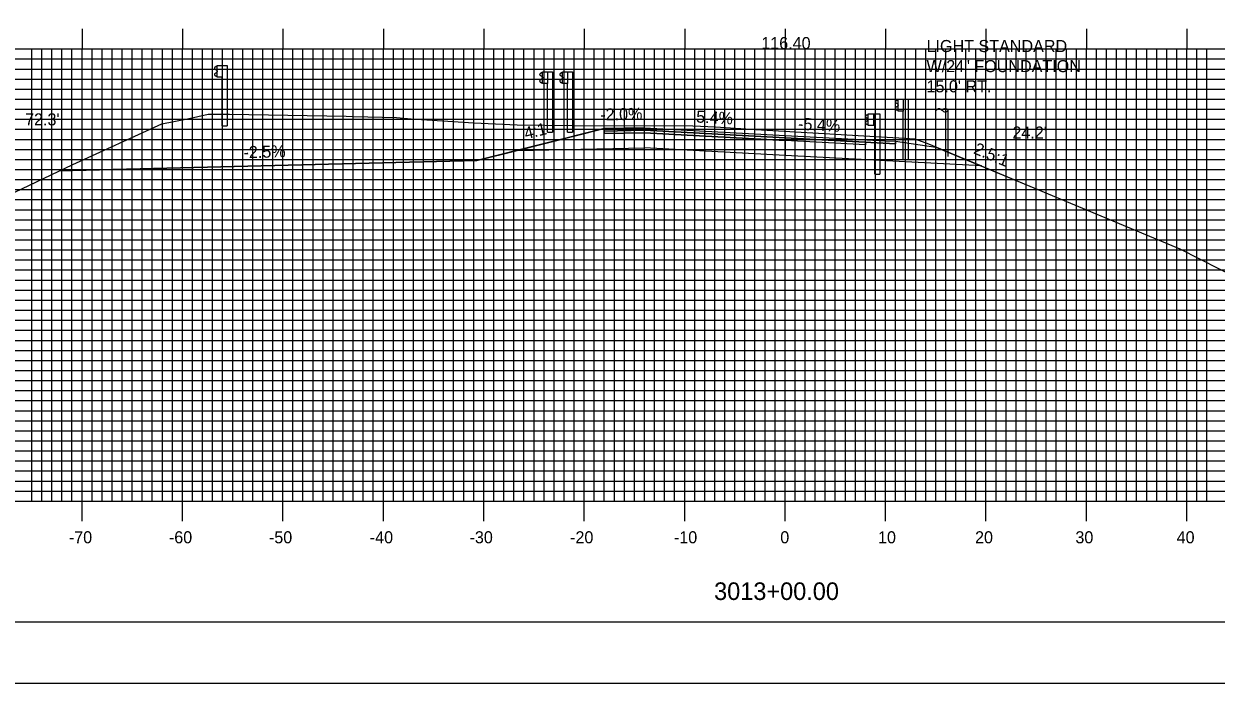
# Model space of a CAD drawing. Extents: x 1684405 to 1684749, y 461260 to 461480.
# Drawn here: x 1684495.4 to 1684614.1, y 461260 to 461325.6 of the extents above; entities that cross this region are included whole.
import ezdxf

# ---------------------------------------------------------------- set-up
doc = ezdxf.new("R2010")
doc.units = 0
for name, color, linetype in [('ANNOTATION', 7, 'Continuous'), ('BORDER', 7, 'Continuous'), ('D_Guardrail_Beam_Rt', 7, 'Continuous'), ('D_Roadway_Centerline', 7, 'Continuous'), ('D_Roadway_Centerline_Text', 7, 'Continuous'), ('D_Roadway_Edge_Shoulder', 7, 'Continuous'), ('D_Roadway_Edge_TW', 7, 'Continuous'), ('D_Roadway_Pavement', 7, 'Continuous'), ('D_Roadway_SlopeLines', 7, 'Continuous'), ('D_Roadway_SubGrade', 7, 'Continuous'), ('D_Text_Standard', 7, 'Continuous'), ('H_V ANNOTATION', 7, 'Continuous'), ('M_Guardrail', 7, 'Continuous'), ('M_Roadway_Centerline', 7, 'Continuous'), ('MAJOR', 7, 'Continuous'), ('MINOR', 7, 'Continuous'), ('PLOT BOUNDARY', 7, 'Continuous'), ('S_Roadway_Centerline', 7, 'Continuous'), ('S_Utilities_Pole_StreetLight', 7, 'Continuous')]:
    doc.layers.add(name, color=color, linetype=linetype)

msp = doc.modelspace()

# ---------------------------------------------------------------- linework, layer by layer
at = {"layer": 'BORDER'}
msp.add_lwpolyline([(1684421.6, 461266.07), (1684741.6, 461266.07), (1684741.6, 461476.07), (1684421.6, 461476.07)], close=True, dxfattribs=at)
at = {"layer": 'D_Guardrail_Beam_Rt'}
for p, q in [((1684579.38, 461316.52), (1684579.24, 461316.42)), ((1684579.24, 461316.27), (1684579.44, 461316.14)), ((1684579.44, 461315.94), (1684579.24, 461315.8)), ((1684579.47, 461316.54), (1684579.4, 461316.52)), ((1684579.47, 461316.62), (1684580.16, 461316.62)), ((1684579.47, 461315.46), (1684579.47, 461316.62)), ((1684579.47, 461316.07), (1684579.47, 461316)), ((1684579.99, 461316.62), (1684579.99, 461315.46)), ((1684580.1, 461316.62), (1684580.1, 461315.46)), ((1684580.16, 461316.62), (1684580.63, 461316.62)), ((1684580.16, 461316.62), (1684580.16, 461315.46)), ((1684580.63, 461316.62), (1684580.63, 461310.62)), ((1684579.24, 461315.66), (1684579.38, 461315.56)), ((1684579.4, 461315.55), (1684579.47, 461315.54)), ((1684580.16, 461315.46), (1684579.47, 461315.46)), ((1684580.14, 461310.62), (1684580.14, 461315.46)), ((1684580.14, 461310.62), (1684580.63, 461310.62))]:
    msp.add_line(p, q, dxfattribs=at)
for centre, major_axis, start_param, end_param in [((1684579.29, 461316.35), (-0.0877, 0), 5.323254, 7.243116), ((1684579.29, 461315.73), (-0.0877, 0), 5.323254, 7.243116), ((1684579.41, 461316.48), (-0.0417, 0), 4.907132, 5.323254), ((1684579.39, 461316.07), (0.0789, 0), 0, 0.959931), ((1684579.39, 461316), (0.0789, 0), 5.323254, 6.283185), ((1684579.41, 461315.59), (-0.0417, 0), 0.959931, 1.376053)]:
    msp.add_ellipse(centre, major_axis=major_axis, ratio=0.995501, start_param=start_param, end_param=end_param, dxfattribs=at)
at = {"layer": 'D_Roadway_Centerline'}
msp.add_lwpolyline([(1684498.93, 461310.93), (1684540.51, 461311.97), (1684544.51, 461312.97), (1684553.2, 461315.15), (1684557.2, 461315.23), (1684571.2, 461314.47), (1684581.2, 461313.93), (1684582.2, 461313.88), (1684586.2, 461313.31), (1684595.4, 461309.48)], dxfattribs=at)
at = {"layer": 'D_Roadway_Edge_Shoulder'}
for points in [[(1684557.2, 461315.23), (1684553.2, 461315.15), (1684553.2, 461314.9), (1684557.2, 461314.98)], [(1684571.2, 461314.47), (1684581.2, 461313.93), (1684581.2, 461313.93), (1684582.2, 461313.88), (1684582.2, 461313.63), (1684571.2, 461314.22)], [(1684571.2, 461314.22), (1684579.2, 461313.79), (1684579.2, 461313.54), (1684571.2, 461313.97)]]:
    msp.add_lwpolyline(points, close=True, dxfattribs=at)
at = {"layer": 'D_Roadway_Edge_TW'}
msp.add_lwpolyline([(1684557.2, 461315.23), (1684571.2, 461314.47), (1684571.2, 461314.22), (1684557.2, 461314.98)], close=True, dxfattribs=at)
at = {"layer": 'D_Roadway_Pavement'}
for points in [[(1684557.2, 461314.98), (1684553.2, 461314.9), (1684553.2, 461314.65), (1684557.2, 461314.73)], [(1684557.2, 461314.98), (1684571.2, 461314.22), (1684571.2, 461313.97), (1684557.2, 461314.73)]]:
    msp.add_lwpolyline(points, close=True, dxfattribs=at)
msp.add_lwpolyline([(1684571.2, 461314.22), (1684571.2, 461313.97)], dxfattribs=at)
msp.add_lwpolyline([(1684571.2, 461314.22), (1684571.2, 461313.97)], dxfattribs=at)
msp.add_lwpolyline([(1684571.2, 461314.22), (1684571.2, 461313.97)], dxfattribs=at)
at = {"layer": 'D_Roadway_SlopeLines'}
for points in [[(1684553.2, 461315.15), (1684540.51, 461311.97)], [(1684540.51, 461311.97), (1684498.93, 461310.93)]]:
    msp.add_lwpolyline(points, dxfattribs=at)
at = {"layer": 'D_Roadway_SubGrade'}
for points in [[(1684557.2, 461314.73), (1684553.2, 461314.65), (1684553.2, 461314.9), (1684553.2, 461315.15), (1684544.51, 461312.97), (1684557.2, 461313.23)], [(1684557.2, 461314.73), (1684571.2, 461313.97), (1684571.2, 461312.47), (1684557.2, 461313.23)], [(1684571.2, 461313.97), (1684571.2, 461314.22), (1684582.2, 461313.63), (1684582.2, 461313.88), (1684586.2, 461313.31), (1684590.75, 461311.42), (1684571.2, 461312.47)]]:
    msp.add_lwpolyline(points, close=True, dxfattribs=at)
at = {"layer": 'M_Guardrail'}
for p, q in [((1684514.56, 461321.33), (1684514.42, 461321.23)), ((1684514.42, 461321.09), (1684514.61, 461320.95)), ((1684514.61, 461320.73), (1684514.42, 461320.6)), ((1684514.66, 461321.35), (1684514.58, 461321.34)), ((1684514.65, 461320.89), (1684514.65, 461320.8)), ((1684514.66, 461321.43), (1684515.15, 461321.43)), ((1684514.66, 461320.26), (1684514.66, 461321.43)), ((1684515.15, 461321.43), (1684515.64, 461321.43)), ((1684515.15, 461321.43), (1684515.15, 461320.26)), ((1684515.64, 461321.43), (1684515.64, 461315.43)), ((1684546.95, 461320.69), (1684546.8, 461320.59)), ((1684547.05, 461320.71), (1684546.96, 461320.7)), ((1684547.05, 461320.79), (1684547.54, 461320.79)), ((1684547.05, 461319.62), (1684547.05, 461320.79)), ((1684547.54, 461320.79), (1684548.03, 461320.79)), ((1684547.54, 461320.79), (1684547.54, 461319.62)), ((1684548.03, 461320.79), (1684548.03, 461314.79)), ((1684548.95, 461320.69), (1684548.8, 461320.59)), ((1684549.05, 461320.71), (1684548.96, 461320.7)), ((1684549.05, 461320.79), (1684549.54, 461320.79)), ((1684549.05, 461319.62), (1684549.05, 461320.79)), ((1684549.54, 461320.79), (1684550.03, 461320.79)), ((1684549.54, 461320.79), (1684549.54, 461319.62)), ((1684550.03, 461320.79), (1684550.03, 461314.79)), ((1684514.42, 461320.45), (1684514.56, 461320.35)), ((1684514.58, 461320.35), (1684514.66, 461320.33)), ((1684515.15, 461320.26), (1684514.66, 461320.26)), ((1684515.15, 461315.43), (1684515.15, 461320.26)), ((1684546.8, 461320.45), (1684547, 461320.31)), ((1684547, 461320.09), (1684546.8, 461319.96)), ((1684546.8, 461319.81), (1684546.95, 461319.71)), ((1684546.96, 461319.71), (1684547.05, 461319.69)), ((1684547.03, 461320.25), (1684547.03, 461320.16)), ((1684547.54, 461319.62), (1684547.05, 461319.62)), ((1684547.54, 461314.79), (1684547.54, 461319.62)), ((1684548.8, 461320.45), (1684549, 461320.31)), ((1684549, 461320.09), (1684548.8, 461319.96)), ((1684548.8, 461319.81), (1684548.95, 461319.71)), ((1684548.96, 461319.71), (1684549.05, 461319.69)), ((1684549.03, 461320.25), (1684549.03, 461320.16)), ((1684549.54, 461319.62), (1684549.05, 461319.62)), ((1684549.54, 461314.79), (1684549.54, 461319.62)), ((1684582.37, 461317.96), (1684582.23, 461317.86)), ((1684582.23, 461317.72), (1684582.43, 461317.59)), ((1684582.43, 461317.37), (1684582.23, 461317.23)), ((1684582.23, 461317.09), (1684582.37, 461316.99)), ((1684582.47, 461317.99), (1684582.39, 461317.97)), ((1684582.46, 461317.52), (1684582.46, 461317.43)), ((1684582.47, 461318.06), (1684582.96, 461318.06)), ((1684582.47, 461316.89), (1684582.47, 461318.06)), ((1684582.96, 461318.06), (1684583.45, 461318.06)), ((1684582.96, 461318.06), (1684582.96, 461316.89)), ((1684583.45, 461318.06), (1684583.45, 461312.06)), ((1684582.39, 461316.98), (1684582.47, 461316.96)), ((1684582.96, 461316.89), (1684582.47, 461316.89)), ((1684582.96, 461312.06), (1684582.96, 461316.89)), ((1684515.15, 461315.43), (1684515.64, 461315.43)), ((1684547.54, 461314.79), (1684548.03, 461314.79)), ((1684549.54, 461314.79), (1684550.03, 461314.79)), ((1684582.96, 461312.06), (1684583.45, 461312.06))]:
    msp.add_line(p, q, dxfattribs=at)
for centre, major_axis, start_param, end_param in [((1684514.47, 461321.16), (-0.0877, 0), 5.323254, 7.243116), ((1684514.47, 461320.53), (-0.0877, 0), 5.323254, 7.243116), ((1684514.59, 461321.3), (-0.0417, 0), 4.886922, 5.323254), ((1684514.57, 461320.89), (0.0789, 0), 0, 0.959931), ((1684514.57, 461320.8), (0.0789, 0), 5.323254, 6.283185), ((1684546.85, 461320.52), (-0.0877, 0), 5.323254, 7.243116), ((1684546.97, 461320.66), (-0.0417, 0), 4.886922, 5.323254), ((1684548.85, 461320.52), (-0.0877, 0), 5.323254, 7.243116), ((1684548.97, 461320.66), (-0.0417, 0), 4.886922, 5.323254), ((1684514.59, 461320.39), (-0.0417, 0), 0.959931, 1.396263), ((1684546.85, 461319.88), (-0.0877, 0), 5.323254, 7.243116), ((1684546.97, 461319.75), (-0.0417, 0), 0.959931, 1.396263), ((1684546.95, 461320.25), (0.0789, 0), 0, 0.959931), ((1684546.95, 461320.16), (0.0789, 0), 5.323254, 6.283185), ((1684548.85, 461319.89), (-0.0877, 0), 5.323254, 7.243116), ((1684548.97, 461319.75), (-0.0417, 0), 0.959931, 1.396263), ((1684548.95, 461320.25), (0.0789, 0), 0, 0.959931), ((1684548.95, 461320.16), (0.0789, 0), 5.323254, 6.283185), ((1684582.28, 461317.79), (-0.0877, 0), 5.323254, 7.243116), ((1684582.28, 461317.16), (-0.0877, 0), 5.323254, 7.243116), ((1684582.4, 461317.93), (-0.0417, 0), 4.886922, 5.323254), ((1684582.4, 461317.02), (-0.0417, 0), 0.959931, 1.396263), ((1684582.38, 461317.52), (0.0789, 0), 0, 0.959931), ((1684582.38, 461317.43), (0.0789, 0), 5.323254, 6.283185)]:
    msp.add_ellipse(centre, major_axis=major_axis, ratio=0.995501, start_param=start_param, end_param=end_param, dxfattribs=at)
at = {"layer": 'MAJOR'}
for p, q in [((1684501.2, 461325.08), (1684501.2, 461323.07)), ((1684511.2, 461325.08), (1684511.2, 461323.07)), ((1684521.2, 461325.08), (1684521.2, 461323.07)), ((1684531.2, 461325.08), (1684531.2, 461323.07)), ((1684541.2, 461325.08), (1684541.2, 461323.07)), ((1684551.2, 461325.08), (1684551.2, 461323.07)), ((1684561.2, 461325.08), (1684561.2, 461323.07)), ((1684571.2, 461325.08), (1684571.2, 461323.07)), ((1684581.2, 461325.08), (1684581.2, 461323.07)), ((1684591.2, 461325.08), (1684591.2, 461323.07)), ((1684601.2, 461325.08), (1684601.2, 461323.07)), ((1684611.2, 461325.08), (1684611.2, 461323.07)), ((1684431.2, 461323.07), (1684711.2, 461323.07)), ((1684431.2, 461323.07), (1684711.2, 461323.07)), ((1684501.2, 461278.07), (1684501.2, 461323.07)), ((1684511.2, 461278.07), (1684511.2, 461323.07)), ((1684521.2, 461278.07), (1684521.2, 461323.07)), ((1684531.2, 461278.07), (1684531.2, 461323.07)), ((1684541.2, 461278.07), (1684541.2, 461323.07)), ((1684551.2, 461278.07), (1684551.2, 461323.07)), ((1684561.2, 461278.07), (1684561.2, 461323.07)), ((1684571.2, 461278.07), (1684571.2, 461323.07)), ((1684581.2, 461278.07), (1684581.2, 461323.07)), ((1684591.2, 461278.07), (1684591.2, 461323.07)), ((1684601.2, 461278.07), (1684601.2, 461323.07)), ((1684611.2, 461278.07), (1684611.2, 461323.07)), ((1684431.2, 461318.07), (1684711.2, 461318.07)), ((1684431.2, 461313.07), (1684711.2, 461313.07)), ((1684431.2, 461308.07), (1684711.2, 461308.07)), ((1684431.2, 461303.07), (1684711.2, 461303.07)), ((1684431.2, 461298.07), (1684711.2, 461298.07)), ((1684431.2, 461293.07), (1684711.2, 461293.07)), ((1684431.2, 461288.07), (1684711.2, 461288.07)), ((1684431.2, 461283.07), (1684711.2, 461283.07)), ((1684431.2, 461278.07), (1684711.2, 461278.07)), ((1684431.2, 461278.07), (1684711.2, 461278.07)), ((1684501.2, 461276.07), (1684501.2, 461278.07)), ((1684511.2, 461276.07), (1684511.2, 461278.07)), ((1684521.2, 461276.07), (1684521.2, 461278.07)), ((1684531.2, 461276.07), (1684531.2, 461278.07)), ((1684541.2, 461276.07), (1684541.2, 461278.07)), ((1684551.2, 461276.07), (1684551.2, 461278.07)), ((1684561.2, 461276.07), (1684561.2, 461278.07)), ((1684571.2, 461276.07), (1684571.2, 461278.07)), ((1684581.2, 461276.07), (1684581.2, 461278.07)), ((1684591.2, 461276.07), (1684591.2, 461278.07)), ((1684601.2, 461276.07), (1684601.2, 461278.07)), ((1684611.2, 461276.07), (1684611.2, 461278.07))]:
    msp.add_line(p, q, dxfattribs=at)
at = {"layer": 'MINOR'}
for p, q in [((1684496.2, 461278.07), (1684496.2, 461323.07)), ((1684497.2, 461278.07), (1684497.2, 461323.07)), ((1684498.2, 461278.07), (1684498.2, 461323.07)), ((1684499.2, 461278.07), (1684499.2, 461323.07)), ((1684500.2, 461278.07), (1684500.2, 461323.07)), ((1684502.2, 461278.07), (1684502.2, 461323.07)), ((1684503.2, 461278.07), (1684503.2, 461323.07)), ((1684504.2, 461278.07), (1684504.2, 461323.07)), ((1684505.2, 461278.07), (1684505.2, 461323.07)), ((1684506.2, 461278.07), (1684506.2, 461323.07)), ((1684507.2, 461278.07), (1684507.2, 461323.07)), ((1684508.2, 461278.07), (1684508.2, 461323.07)), ((1684509.2, 461278.07), (1684509.2, 461323.07)), ((1684510.2, 461278.07), (1684510.2, 461323.07)), ((1684512.2, 461278.07), (1684512.2, 461323.07)), ((1684513.2, 461278.07), (1684513.2, 461323.07)), ((1684514.2, 461278.07), (1684514.2, 461323.07)), ((1684515.2, 461278.07), (1684515.2, 461323.07)), ((1684516.2, 461278.07), (1684516.2, 461323.07)), ((1684517.2, 461278.07), (1684517.2, 461323.07)), ((1684518.2, 461278.07), (1684518.2, 461323.07)), ((1684519.2, 461278.07), (1684519.2, 461323.07)), ((1684520.2, 461278.07), (1684520.2, 461323.07)), ((1684522.2, 461278.07), (1684522.2, 461323.07)), ((1684523.2, 461278.07), (1684523.2, 461323.07)), ((1684524.2, 461278.07), (1684524.2, 461323.07)), ((1684525.2, 461278.07), (1684525.2, 461323.07)), ((1684526.2, 461278.07), (1684526.2, 461323.07)), ((1684527.2, 461278.07), (1684527.2, 461323.07)), ((1684528.2, 461278.07), (1684528.2, 461323.07)), ((1684529.2, 461278.07), (1684529.2, 461323.07)), ((1684530.2, 461278.07), (1684530.2, 461323.07)), ((1684532.2, 461278.07), (1684532.2, 461323.07)), ((1684533.2, 461278.07), (1684533.2, 461323.07)), ((1684534.2, 461278.07), (1684534.2, 461323.07)), ((1684535.2, 461278.07), (1684535.2, 461323.07)), ((1684536.2, 461278.07), (1684536.2, 461323.07)), ((1684537.2, 461278.07), (1684537.2, 461323.07)), ((1684538.2, 461278.07), (1684538.2, 461323.07)), ((1684539.2, 461278.07), (1684539.2, 461323.07)), ((1684540.2, 461278.07), (1684540.2, 461323.07)), ((1684542.2, 461278.07), (1684542.2, 461323.07)), ((1684543.2, 461278.07), (1684543.2, 461323.07)), ((1684544.2, 461278.07), (1684544.2, 461323.07)), ((1684545.2, 461278.07), (1684545.2, 461323.07)), ((1684546.2, 461278.07), (1684546.2, 461323.07)), ((1684547.2, 461278.07), (1684547.2, 461323.07)), ((1684548.2, 461278.07), (1684548.2, 461323.07)), ((1684549.2, 461278.07), (1684549.2, 461323.07)), ((1684550.2, 461278.07), (1684550.2, 461323.07)), ((1684552.2, 461278.07), (1684552.2, 461323.07)), ((1684553.2, 461278.07), (1684553.2, 461323.07)), ((1684554.2, 461278.07), (1684554.2, 461323.07)), ((1684555.2, 461278.07), (1684555.2, 461323.07)), ((1684556.2, 461278.07), (1684556.2, 461323.07)), ((1684557.2, 461278.07), (1684557.2, 461323.07)), ((1684558.2, 461278.07), (1684558.2, 461323.07)), ((1684559.2, 461278.07), (1684559.2, 461323.07)), ((1684560.2, 461278.07), (1684560.2, 461323.07)), ((1684562.2, 461278.07), (1684562.2, 461323.07)), ((1684563.2, 461278.07), (1684563.2, 461323.07)), ((1684564.2, 461278.07), (1684564.2, 461323.07)), ((1684565.2, 461278.07), (1684565.2, 461323.07)), ((1684566.2, 461278.07), (1684566.2, 461323.07)), ((1684567.2, 461278.07), (1684567.2, 461323.07)), ((1684568.2, 461278.07), (1684568.2, 461323.07)), ((1684569.2, 461278.07), (1684569.2, 461323.07)), ((1684570.2, 461278.07), (1684570.2, 461323.07)), ((1684572.2, 461278.07), (1684572.2, 461323.07)), ((1684573.2, 461278.07), (1684573.2, 461323.07)), ((1684574.2, 461278.07), (1684574.2, 461323.07)), ((1684575.2, 461278.07), (1684575.2, 461323.07)), ((1684576.2, 461278.07), (1684576.2, 461323.07)), ((1684577.2, 461278.07), (1684577.2, 461323.07)), ((1684578.2, 461278.07), (1684578.2, 461323.07)), ((1684579.2, 461278.07), (1684579.2, 461323.07)), ((1684580.2, 461278.07), (1684580.2, 461323.07)), ((1684582.2, 461278.07), (1684582.2, 461323.07)), ((1684583.2, 461278.07), (1684583.2, 461323.07)), ((1684584.2, 461278.07), (1684584.2, 461323.07)), ((1684585.2, 461278.07), (1684585.2, 461323.07)), ((1684586.2, 461278.07), (1684586.2, 461323.07)), ((1684587.2, 461278.07), (1684587.2, 461323.07)), ((1684588.2, 461278.07), (1684588.2, 461323.07)), ((1684589.2, 461278.07), (1684589.2, 461323.07)), ((1684590.2, 461278.07), (1684590.2, 461323.07)), ((1684592.2, 461278.07), (1684592.2, 461323.07)), ((1684593.2, 461278.07), (1684593.2, 461323.07)), ((1684594.2, 461278.07), (1684594.2, 461323.07)), ((1684595.2, 461278.07), (1684595.2, 461323.07)), ((1684596.2, 461278.07), (1684596.2, 461323.07)), ((1684597.2, 461278.07), (1684597.2, 461323.07)), ((1684598.2, 461278.07), (1684598.2, 461323.07)), ((1684599.2, 461278.07), (1684599.2, 461323.07)), ((1684600.2, 461278.07), (1684600.2, 461323.07)), ((1684602.2, 461278.07), (1684602.2, 461323.07)), ((1684603.2, 461278.07), (1684603.2, 461323.07)), ((1684604.2, 461278.07), (1684604.2, 461323.07)), ((1684605.2, 461278.07), (1684605.2, 461323.07)), ((1684606.2, 461278.07), (1684606.2, 461323.07)), ((1684607.2, 461278.07), (1684607.2, 461323.07)), ((1684608.2, 461278.07), (1684608.2, 461323.07)), ((1684609.2, 461278.07), (1684609.2, 461323.07)), ((1684610.2, 461278.07), (1684610.2, 461323.07)), ((1684612.2, 461278.07), (1684612.2, 461323.07)), ((1684613.2, 461278.07), (1684613.2, 461323.07)), ((1684431.2, 461322.07), (1684711.2, 461322.07)), ((1684431.2, 461321.07), (1684711.2, 461321.07)), ((1684431.2, 461320.07), (1684711.2, 461320.07)), ((1684431.2, 461319.07), (1684711.2, 461319.07)), ((1684431.2, 461317.07), (1684711.2, 461317.07)), ((1684431.2, 461316.07), (1684711.2, 461316.07)), ((1684431.2, 461315.07), (1684711.2, 461315.07)), ((1684431.2, 461314.07), (1684711.2, 461314.07)), ((1684431.2, 461312.07), (1684711.2, 461312.07)), ((1684431.2, 461311.07), (1684711.2, 461311.07)), ((1684431.2, 461310.07), (1684711.2, 461310.07)), ((1684431.2, 461309.07), (1684711.2, 461309.07)), ((1684431.2, 461307.07), (1684711.2, 461307.07)), ((1684431.2, 461306.07), (1684711.2, 461306.07)), ((1684431.2, 461305.07), (1684711.2, 461305.07)), ((1684431.2, 461304.07), (1684711.2, 461304.07)), ((1684431.2, 461302.07), (1684711.2, 461302.07)), ((1684431.2, 461301.07), (1684711.2, 461301.07)), ((1684431.2, 461300.07), (1684711.2, 461300.07)), ((1684431.2, 461299.07), (1684711.2, 461299.07)), ((1684431.2, 461297.07), (1684711.2, 461297.07)), ((1684431.2, 461296.07), (1684711.2, 461296.07)), ((1684431.2, 461295.07), (1684711.2, 461295.07)), ((1684431.2, 461294.07), (1684711.2, 461294.07)), ((1684431.2, 461292.07), (1684711.2, 461292.07)), ((1684431.2, 461291.07), (1684711.2, 461291.07)), ((1684431.2, 461290.07), (1684711.2, 461290.07)), ((1684431.2, 461289.07), (1684711.2, 461289.07)), ((1684431.2, 461287.07), (1684711.2, 461287.07)), ((1684431.2, 461286.07), (1684711.2, 461286.07)), ((1684431.2, 461285.07), (1684711.2, 461285.07)), ((1684431.2, 461284.07), (1684711.2, 461284.07)), ((1684431.2, 461282.07), (1684711.2, 461282.07)), ((1684431.2, 461281.07), (1684711.2, 461281.07)), ((1684431.2, 461280.07), (1684711.2, 461280.07)), ((1684431.2, 461279.07), (1684711.2, 461279.07))]:
    msp.add_line(p, q, dxfattribs=at)
at = {"layer": 'PLOT BOUNDARY'}
msp.add_lwpolyline([(1684405.42, 461259.95), (1684745.42, 461259.95), (1684745.42, 461479.95), (1684405.42, 461479.95)], close=True, dxfattribs=at)
at = {"layer": 'S_Roadway_Centerline'}
msp.add_lwpolyline([(1684492.33, 461307.78), (1684500.28, 461311.57), (1684509.14, 461315.61), (1684511.7, 461316.1), (1684513.75, 461316.57), (1684515.87, 461316.57), (1684527.5, 461316.37), (1684528.23, 461316.34), (1684532.51, 461316.23), (1684533.97, 461316.13), (1684540.2, 461315.73), (1684544.54, 461315.5), (1684550.07, 461315.44), (1684562.01, 461315.41), (1684564.28, 461315.32), (1684568.29, 461315.06), (1684578.47, 461314.46), (1684583.09, 461314.19), (1684584.13, 461314.13), (1684585.49, 461313.61), (1684610.5, 461303.19), (1684616.37, 461300.2)], dxfattribs=at)
at = {"layer": 'S_Utilities_Pole_StreetLight'}
for p, q in [((1684586.2, 461316.97), (1684586.36, 461317.08)), ((1684586.67, 461317.08), (1684586.83, 461316.97)), ((1684586.98, 461317.08), (1684586.83, 461316.97)), ((1684587.45, 461316.97), (1684587.3, 461317.08)), ((1684586.2, 461312.35), (1684586.2, 461316.97)), ((1684586.83, 461316.97), (1684586.98, 461316.85)), ((1684587.3, 461316.85), (1684587.45, 461316.97)), ((1684587.45, 461312.35), (1684587.45, 461316.97))]:
    msp.add_line(p, q, dxfattribs=at)
for centre, start, end in [((1684586.52, 461316.85), 90, 125.2644), ((1684586.52, 461316.85), 54.7356, 90), ((1684587.14, 461316.85), 90, 125.2644), ((1684587.14, 461316.85), 54.7356, 90), ((1684587.14, 461317.08), 234.7356, 270), ((1684587.14, 461317.08), 270, 305.2644)]:
    msp.add_arc(centre, 0.271, start, end, dxfattribs=at)

# ---------------------------------------------------------------- texts
at = {"layer": 'ANNOTATION'}
for s, p in [('LIGHT STANDARD ', (1684585.28, 461322.76)), ('W/24" FOUNDATION', (1684585.28, 461320.76)), ("15.0' RT.", (1684585.28, 461318.75))]:
    msp.add_text(s, height=1.2, dxfattribs=at).set_placement(p)
for s, rotation, p in [('-2.0%', 1.1458, (1684552.81, 461315.94)), ('5.4%', 356.909, (1684562.32, 461315.75)), ('-5.4%', 356.909, (1684572.47, 461315.04)), ('4:1', 14.0362, (1684545.39, 461314.06)), ('-2.5%', 1.4415, (1684517.29, 461312.19)), ('2.5:1', 337.3926, (1684589.88, 461312.69))]:
    msp.add_text(s, height=1.2, rotation=rotation, dxfattribs=at).set_placement(p)
at = {"layer": 'D_Roadway_Centerline_Text'}
msp.add_text('116.40', height=1.2, dxfattribs=at).set_placement((1684568.83, 461323.05))
at = {"layer": 'D_Text_Standard'}
for s, p in [("72.3'", (1684495.53, 461315.46)), ("24.2'", (1684593.83, 461314.15))]:
    msp.add_text(s, height=1.2, dxfattribs=at).set_placement(p)
at = {"layer": 'H_V ANNOTATION'}
for s, height, p in [('-70', 1.2, (1684499.89, 461273.87)), ('-60', 1.2, (1684509.85, 461273.87)), ('-50', 1.2, (1684519.81, 461273.87)), ('-40', 1.2, (1684529.85, 461273.87)), ('-30', 1.2, (1684539.78, 461273.87)), ('-20', 1.2, (1684549.79, 461273.87)), ('-10', 1.2, (1684560.13, 461273.87)), ('0', 1.2, (1684570.72, 461273.87)), ('10', 1.2, (1684580.45, 461273.87)), ('20', 1.2, (1684590.11, 461273.87)), ('30', 1.2, (1684600.1, 461273.87)), ('40', 1.2, (1684610.18, 461273.87)), ('3013+00.00', 1.75, (1684564.13, 461268.23))]:
    msp.add_text(s, height=height, dxfattribs=at).set_placement(p)
at = {"layer": 'M_Roadway_Centerline'}
for s, p in [('C', (1684532.5, 461316.23)), ('L', (1684532.51, 461316.22)), ('C', (1684564.27, 461315.32)), ('L', (1684564.28, 461315.31))]:
    msp.add_text(s, height=0.0146, dxfattribs=at).set_placement(p)

doc.saveas('drawing.dxf')
